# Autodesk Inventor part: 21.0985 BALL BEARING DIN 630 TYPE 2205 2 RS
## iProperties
IsCustomPart: 1
Created: 2006-02
Part Number: 21.0985 BALL BEARING DIN 630 TYPE 2205 2 RS
Material: Steel, Mild
Description: Self-Aligning Ball Bearing
Document SubType Name: Modeling
Standard: DIN 630
Designer: Andy Moles
Standards Organization: DIN
Language: en-US
Size Designation: 2205 - 25 x 52 x 18
Categories: <MemberInstance><Categories><Category DisplayName="Shaft Parts" InternalName="7f7aeb1f-a693-4053-b835-cee3144e0d98" Mnemonic="SHFT"><Category DisplayName="Beari
Density: 1 g/cm^3
Author: Andy Moles
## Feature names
1. Body [Revolution]
2. Fillet1
3. Ball1 [Revolution]
4. Ball2 [Revolution]
5. Balls1 [Circular Pattern]
6. Balls2 [Rectangular Pattern]
